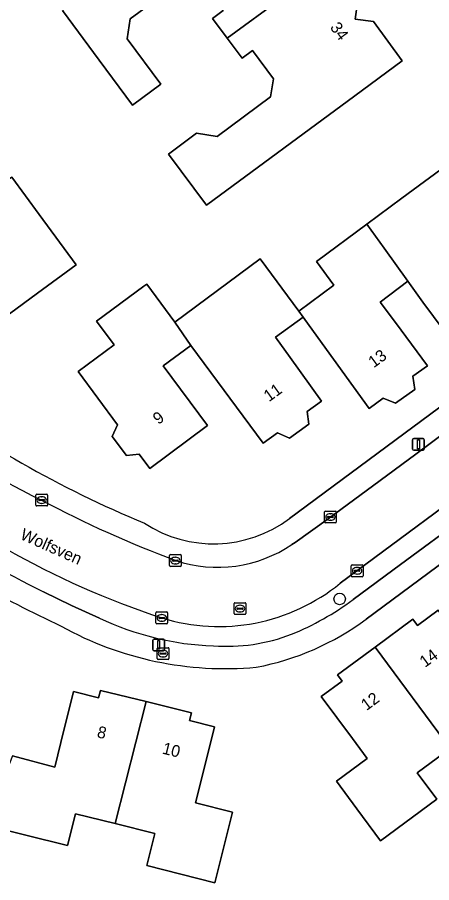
# Model space of a CAD drawing. Extents: x 163426 to 164192, y 380329 to 381641.
# Drawn here: x 163794 to 163829.1, y 381099.2 to 381172.6 of the extents above; entities that cross this region are included whole.
import ezdxf

# ---------------------------------------------------------------- set-up
doc = ezdxf.new("R2010")
doc.units = 0
for name, color, linetype in [('IMGEO_Boom', 7, 'Continuous'), ('IMGEO_Brandkraan', 7, 'Continuous'), ('IMGEO_Erf', 7, 'Continuous'), ('IMGEO_Kolk', 7, 'Continuous'), ('IMGEO_Lichtmast', 7, 'Continuous'), ('IMGEO_Openbare_ruimte_label', 7, 'Continuous'), ('IMGEO_Pand', 7, 'Continuous'), ('IMGEO_Pand_nummerreeks', 7, 'Continuous'), ('IMGEO_Parkeervlak_open', 7, 'Continuous'), ('IMGEO_Rijbaan_lokaal_open', 7, 'Continuous'), ('IMGEO_Rioolput', 7, 'Continuous'), ('IMGEO_Voetpad_open', 7, 'Continuous')]:
    doc.layers.add(name, color=color, linetype=linetype)

msp = doc.modelspace()

# ---------------------------------------------------------------- linework, layer by layer
at = {"layer": 'IMGEO_Boom'}
msp.add_circle((163821.325, 381123.271), 0.489, dxfattribs=at)
at = {"layer": 'IMGEO_Brandkraan'}
for p, q in [((163805.85, 381118.213), (163805.85, 381119.065)), ((163805.925, 381119.139), (163806.777, 381119.139)), ((163806.109, 381118.633), (163806.109, 381118.645)), ((163806.547, 381118.596), (163806.149, 381118.596)), ((163806.152, 381118.682), (163806.55, 381118.682)), ((163806.338, 381118.919), (163806.363, 381118.919)), ((163806.593, 381118.645), (163806.593, 381118.633)), ((163806.851, 381119.065), (163806.851, 381118.213)), ((163806.777, 381118.139), (163805.925, 381118.139)), ((163806.361, 381118.359), (163806.336, 381118.359))]:
    msp.add_line(p, q, dxfattribs=at)
for points in [[(163805.85, 381118.213), (163805.85, 381119.065)], [(163805.925, 381119.139), (163806.777, 381119.139)], [(163806.851, 381119.065), (163806.851, 381118.213)], [(163806.777, 381118.139), (163805.925, 381118.139)]]:
    msp.add_lwpolyline(points, dxfattribs=at)
for centre, radius, start, end in [((163805.927, 381119.063), 0.0765, 91.55205, 178.44795), ((163805.927, 381119.063), 0.0765, 91.55205, 178.44795), ((163806.149, 381118.642), 0.0403, 85.87752, 175.75265), ((163806.146, 381118.632), 0.0366, 178.93798, 274.71019), ((163806.55, 381118.639), 0.043, 264.86636, 352.45326), ((163806.554, 381118.644), 0.0386, 1.73085, 96.63898), ((163806.775, 381119.063), 0.0765, 1.55205, 88.44795), ((163806.775, 381119.063), 0.0765, 1.55205, 88.44795), ((163805.927, 381118.215), 0.0765, 181.55205, 268.44795), ((163805.927, 381118.215), 0.0765, 181.55205, 268.44795), ((163806.775, 381118.215), 0.0765, 271.55205, 358.44795), ((163806.775, 381118.215), 0.0765, 271.55205, 358.44795)]:
    msp.add_arc(centre, radius, start, end, dxfattribs=at)
for centre, major_axis, ratio, start_param, end_param in [((163806.337, 381118.639), (-0.387, 0.002), 0.722429, 4.712389, 7.853982), ((163806.362, 381118.639), (-0.39, 0.002), 0.717154, 1.570796, 4.712389)]:
    msp.add_ellipse(centre, major_axis=major_axis, ratio=ratio, start_param=start_param, end_param=end_param, dxfattribs=at)
at = {"layer": 'IMGEO_Erf'}
for points in [[(163808.098, 381175.797), (163803.557, 381172.436), (163803.32, 381170.757), (163806.172, 381166.906), (163803.761, 381165.12), (163800.933, 381168.938), (163797.815, 381173.15)], [(163823.048, 381175.267), (163822.643, 381172.432), (163824.185, 381172.212), (163826.637, 381168.889), (163822.614, 381165.921), (163810.036, 381156.641), (163806.817, 381160.989), (163809.196, 381162.75), (163810.928, 381162.477), (163815.469, 381165.839), (163815.714, 381167.372), (163813.94, 381169.768), (163813.047, 381169.11), (163811.798, 381170.798), (163810.549, 381172.486), (163811.441, 381173.144)], [(163831.091, 381144.772), (163828.366, 381148.43), (163827.112, 381150.199), (163824.75, 381148.44), (163826.045, 381146.701), (163828.772, 381143.04), (163827.539, 381142.153), (163827.706, 381141.032), (163826.045, 381139.855), (163825.025, 381140.29), (163823.826, 381139.407), (163819.474, 381145.443), (163818.239, 381147.156), (163815.888, 381145.462), (163817.123, 381143.748), (163819.788, 381140.05), (163818.564, 381139.167), (163818.724, 381138.092), (163817.063, 381136.915), (163816.044, 381137.35), (163814.834, 381136.478), (163808.708, 381144.764), (163806.375, 381143.039), (163810.128, 381137.963), (163805.221, 381134.335), (163804.334, 381135.534), (163803.239, 381135.422), (163802.051, 381137.037), (163802.48, 381138.042), (163799.148, 381142.548), (163802.197, 381144.803), (163800.71, 381146.814), (163804.731, 381149.787), (163804.974, 381149.966), (163807.353, 381146.748), (163814.593, 381152.101), (163817.864, 381147.677), (163820.841, 381149.877), (163819.354, 381151.889), (163823.618, 381155.041), (163826.6, 381157.234), (163830.864, 381160.386)], [(163793.533, 381159.015), (163795.851, 381155.871), (163798.995, 381151.607), (163795.715, 381149.189), (163793.332, 381147.432)], [(163817.071, 381130.093), (163847.678, 381152.747)], [(163851.582, 381142.287), (163823.576, 381121.569)], [(163793.575, 381109.96), (163797.188, 381109.011), (163797.698, 381111.091), (163798.761, 381115.426), (163800.89, 381114.881), (163801.053, 381115.52), (163804.907, 381114.568), (163808.761, 381113.616), (163808.597, 381112.979), (163810.719, 381112.431), (163809.643, 381108.113), (163809.113, 381105.987), (163812.245, 381105.207), (163811.562, 381102.482), (163810.744, 381099.218), (163804.976, 381100.669), (163805.657, 381103.379), (163802.299, 381104.224), (163798.941, 381105.068), (163798.26, 381102.358), (163791.258, 381104.106)]]:
    msp.add_lwpolyline(points, dxfattribs=at)
msp.add_lwpolyline([(163832.339, 381118.744), (163833.595, 381117.047), (163838.652, 381120.79), (163840.369, 381118.468), (163842.369, 381115.763), (163835.137, 381110.417), (163833.474, 381112.667), (163830.686, 381110.606), (163827.897, 381108.544), (163829.56, 381106.294), (163824.787, 381102.765), (163822.772, 381105.488), (163821.044, 381107.824), (163823.646, 381109.743), (163822.404, 381111.428), (163819.765, 381115.007), (163821.537, 381116.304), (163821.148, 381116.836), (163824.334, 381119.194), (163827.519, 381121.551), (163827.911, 381121.018), (163829.688, 381122.325)], close=True, dxfattribs=at)
for centre, radius, start, end in [((163840.706, 381216.197), 93.669, 233.26319, 247.44192), ((163810.638, 381138.638), 10.696, 236.74433, 306.97221), ((163850.773, 381233.409), 124.335, 237.116, 244.73978), ((163810.061, 381139.733), 22.64, 280.68675, 306.65263), ((163811.628, 381146.059), 28.695, 240.99562, 275.25988)]:
    msp.add_arc(centre, radius, start, end, dxfattribs=at)
at = {"layer": 'IMGEO_Kolk'}
for p, q in [((163795.563, 381131.229), (163795.563, 381132.081)), ((163795.638, 381132.155), (163796.49, 381132.155)), ((163795.865, 381131.698), (163796.263, 381131.698)), ((163796.051, 381131.935), (163796.076, 381131.935)), ((163796.564, 381132.081), (163796.564, 381131.229)), ((163796.49, 381131.155), (163795.638, 381131.155)), ((163795.822, 381131.649), (163795.822, 381131.661)), ((163796.26, 381131.612), (163795.862, 381131.612)), ((163796.074, 381131.375), (163796.049, 381131.375)), ((163796.306, 381131.661), (163796.306, 381131.649)), ((163820.041, 381129.792), (163820.041, 381130.644)), ((163820.116, 381130.718), (163820.968, 381130.718)), ((163820.3, 381130.212), (163820.3, 381130.224)), ((163820.343, 381130.261), (163820.741, 381130.261)), ((163820.529, 381130.498), (163820.554, 381130.498)), ((163820.784, 381130.224), (163820.784, 381130.212)), ((163821.042, 381130.644), (163821.042, 381129.792)), ((163820.968, 381129.718), (163820.116, 381129.718)), ((163820.738, 381130.175), (163820.34, 381130.175)), ((163820.552, 381129.938), (163820.527, 381129.938)), ((163806.897, 381126.103), (163806.897, 381126.955)), ((163806.972, 381127.029), (163807.824, 381127.029)), ((163807.156, 381126.523), (163807.156, 381126.535)), ((163807.199, 381126.572), (163807.597, 381126.572)), ((163807.385, 381126.809), (163807.41, 381126.809)), ((163807.64, 381126.535), (163807.64, 381126.523)), ((163807.898, 381126.955), (163807.898, 381126.103)), ((163807.824, 381126.029), (163806.972, 381126.029)), ((163807.594, 381126.486), (163807.196, 381126.486)), ((163807.408, 381126.249), (163807.383, 381126.249)), ((163822.303, 381125.232), (163822.303, 381126.084)), ((163822.378, 381126.158), (163823.23, 381126.158)), ((163822.791, 381125.938), (163822.816, 381125.938)), ((163823.304, 381126.084), (163823.304, 381125.232)), ((163823.23, 381125.158), (163822.378, 381125.158)), ((163822.562, 381125.652), (163822.562, 381125.664)), ((163823, 381125.615), (163822.602, 381125.615)), ((163822.605, 381125.701), (163823.003, 381125.701)), ((163822.814, 381125.378), (163822.789, 381125.378)), ((163823.046, 381125.664), (163823.046, 381125.652)), ((163805.816, 381122.167), (163806.668, 381122.167)), ((163805.741, 381121.241), (163805.741, 381122.093)), ((163806, 381121.661), (163806, 381121.673)), ((163806.438, 381121.624), (163806.04, 381121.624)), ((163806.043, 381121.71), (163806.441, 381121.71)), ((163806.229, 381121.947), (163806.254, 381121.947)), ((163806.484, 381121.673), (163806.484, 381121.661)), ((163806.742, 381122.093), (163806.742, 381121.241)), ((163806.668, 381121.167), (163805.816, 381121.167)), ((163806.252, 381121.387), (163806.227, 381121.387))]:
    msp.add_line(p, q, dxfattribs=at)
for points in [[(163795.563, 381131.229), (163795.563, 381132.081)], [(163795.638, 381132.155), (163796.49, 381132.155)], [(163796.564, 381132.081), (163796.564, 381131.229)], [(163796.49, 381131.155), (163795.638, 381131.155)], [(163820.041, 381129.792), (163820.041, 381130.644)], [(163820.116, 381130.718), (163820.968, 381130.718)], [(163821.042, 381130.644), (163821.042, 381129.792)], [(163820.968, 381129.718), (163820.116, 381129.718)], [(163806.897, 381126.103), (163806.897, 381126.955)], [(163806.972, 381127.029), (163807.824, 381127.029)], [(163807.898, 381126.955), (163807.898, 381126.103)], [(163807.824, 381126.029), (163806.972, 381126.029)], [(163822.303, 381125.232), (163822.303, 381126.084)], [(163822.378, 381126.158), (163823.23, 381126.158)], [(163823.304, 381126.084), (163823.304, 381125.232)], [(163823.23, 381125.158), (163822.378, 381125.158)], [(163805.816, 381122.167), (163806.668, 381122.167)], [(163805.741, 381121.241), (163805.741, 381122.093)], [(163806.742, 381122.093), (163806.742, 381121.241)], [(163806.668, 381121.167), (163805.816, 381121.167)]]:
    msp.add_lwpolyline(points, dxfattribs=at)
for centre, radius, start, end in [((163795.64, 381132.079), 0.0765, 91.55205, 178.44795), ((163795.64, 381132.079), 0.0765, 91.55205, 178.44795), ((163795.862, 381131.658), 0.0403, 85.87752, 175.75265), ((163796.267, 381131.66), 0.0386, 1.73085, 96.63898), ((163796.488, 381132.079), 0.0765, 1.55205, 88.44795), ((163796.488, 381132.079), 0.0765, 1.55205, 88.44795), ((163795.64, 381131.231), 0.0765, 181.55205, 268.44795), ((163795.64, 381131.231), 0.0765, 181.55205, 268.44795), ((163795.859, 381131.648), 0.0366, 178.93798, 274.71019), ((163796.263, 381131.655), 0.043, 264.86636, 352.45326), ((163796.488, 381131.231), 0.0765, 271.55205, 358.44795), ((163796.488, 381131.231), 0.0765, 271.55205, 358.44795), ((163820.118, 381130.642), 0.0765, 91.55205, 178.44795), ((163820.118, 381130.642), 0.0765, 91.55205, 178.44795), ((163820.34, 381130.221), 0.0403, 85.87752, 175.75265), ((163820.337, 381130.211), 0.0366, 178.93798, 274.71019), ((163820.741, 381130.218), 0.043, 264.86636, 352.45326), ((163820.745, 381130.223), 0.0386, 1.73085, 96.63898), ((163820.966, 381130.642), 0.0765, 1.55205, 88.44795), ((163820.966, 381130.642), 0.0765, 1.55205, 88.44795), ((163820.118, 381129.794), 0.0765, 181.55205, 268.44795), ((163820.118, 381129.794), 0.0765, 181.55205, 268.44795), ((163820.966, 381129.794), 0.0765, 271.55205, 358.44795), ((163820.966, 381129.794), 0.0765, 271.55205, 358.44795), ((163806.974, 381126.953), 0.0765, 91.55205, 178.44795), ((163806.974, 381126.953), 0.0765, 91.55205, 178.44795), ((163807.196, 381126.532), 0.0403, 85.87752, 175.75265), ((163807.601, 381126.534), 0.0386, 1.73085, 96.63898), ((163807.822, 381126.953), 0.0765, 1.55205, 88.44795), ((163807.822, 381126.953), 0.0765, 1.55205, 88.44795), ((163806.974, 381126.105), 0.0765, 181.55205, 268.44795), ((163806.974, 381126.105), 0.0765, 181.55205, 268.44795), ((163807.193, 381126.522), 0.0366, 178.93798, 274.71019), ((163807.597, 381126.529), 0.043, 264.86636, 352.45326), ((163807.822, 381126.105), 0.0765, 271.55205, 358.44795), ((163807.822, 381126.105), 0.0765, 271.55205, 358.44795), ((163822.38, 381126.082), 0.0765, 91.55205, 178.44795), ((163822.38, 381126.082), 0.0765, 91.55205, 178.44795), ((163823.228, 381126.082), 0.0765, 1.55205, 88.44795), ((163823.228, 381126.082), 0.0765, 1.55205, 88.44795), ((163822.38, 381125.234), 0.0765, 181.55205, 268.44795), ((163822.38, 381125.234), 0.0765, 181.55205, 268.44795), ((163822.602, 381125.661), 0.0403, 85.87752, 175.75265), ((163822.599, 381125.651), 0.0366, 178.93798, 274.71019), ((163823.003, 381125.658), 0.043, 264.86636, 352.45326), ((163823.007, 381125.663), 0.0386, 1.73085, 96.63898), ((163823.228, 381125.234), 0.0765, 271.55205, 358.44795), ((163823.228, 381125.234), 0.0765, 271.55205, 358.44795), ((163805.818, 381122.091), 0.0765, 91.55205, 178.44795), ((163805.818, 381122.091), 0.0765, 91.55205, 178.44795), ((163806.666, 381122.091), 0.0765, 1.55205, 88.44795), ((163806.666, 381122.091), 0.0765, 1.55205, 88.44795), ((163806.04, 381121.67), 0.0403, 85.87752, 175.75265), ((163806.037, 381121.66), 0.0366, 178.93798, 274.71019), ((163806.441, 381121.667), 0.043, 264.86636, 352.45326), ((163806.445, 381121.672), 0.0386, 1.73085, 96.63898), ((163805.818, 381121.243), 0.0765, 181.55205, 268.44795), ((163805.818, 381121.243), 0.0765, 181.55205, 268.44795), ((163806.666, 381121.243), 0.0765, 271.55205, 358.44795), ((163806.666, 381121.243), 0.0765, 271.55205, 358.44795)]:
    msp.add_arc(centre, radius, start, end, dxfattribs=at)
for centre, major_axis, ratio, start_param, end_param in [((163796.05, 381131.655), (-0.387, 0.002), 0.722429, 4.712389, 7.853982), ((163796.075, 381131.655), (-0.39, 0.002), 0.717154, 1.570796, 4.712389), ((163820.528, 381130.218), (-0.387, 0.002), 0.722429, 4.712389, 7.853982), ((163820.553, 381130.218), (-0.39, 0.002), 0.717154, 1.570796, 4.712389), ((163807.384, 381126.529), (-0.387, 0.002), 0.722429, 4.712389, 7.853982), ((163807.409, 381126.529), (-0.39, 0.002), 0.717154, 1.570796, 4.712389), ((163822.79, 381125.658), (-0.387, 0.002), 0.722429, 4.712389, 7.853982), ((163822.815, 381125.658), (-0.39, 0.002), 0.717154, 1.570796, 4.712389), ((163806.228, 381121.667), (-0.387, 0.002), 0.722429, 4.712389, 7.853982), ((163806.253, 381121.667), (-0.39, 0.002), 0.717154, 1.570796, 4.712389)]:
    msp.add_ellipse(centre, major_axis=major_axis, ratio=ratio, start_param=start_param, end_param=end_param, dxfattribs=at)
at = {"layer": 'IMGEO_Lichtmast'}
for p, q in [((163827.612, 381136.872), (163828.402, 381136.872)), ((163828.402, 381136.872), (163827.612, 381136.872)), ((163827.512, 381135.972), (163827.512, 381136.772)), ((163827.512, 381136.772), (163827.512, 381135.972)), ((163828.502, 381136.772), (163828.502, 381135.972)), ((163828.502, 381135.972), (163828.502, 381136.772)), ((163828.402, 381135.872), (163827.612, 381135.872)), ((163827.612, 381135.872), (163828.402, 381135.872)), ((163805.494, 381118.976), (163805.494, 381119.776)), ((163805.494, 381119.776), (163805.494, 381118.976)), ((163805.594, 381119.876), (163806.384, 381119.876)), ((163806.384, 381119.876), (163805.594, 381119.876)), ((163806.484, 381119.776), (163806.484, 381118.976)), ((163806.484, 381118.976), (163806.484, 381119.776)), ((163806.384, 381118.876), (163805.594, 381118.876)), ((163805.594, 381118.876), (163806.384, 381118.876))]:
    msp.add_line(p, q, dxfattribs=at)
for points in [[(163827.932, 381136.747), (163828.082, 381136.747), (163828.082, 381135.997), (163827.932, 381135.997), (163827.932, 381136.747)], [(163805.914, 381119.751), (163806.064, 381119.751), (163806.064, 381119.001), (163805.914, 381119.001), (163805.914, 381119.751)]]:
    msp.add_lwpolyline(points, dxfattribs=at)
for centre, start, end in [((163827.612, 381136.772), 90, 180), ((163827.612, 381136.772), 90, 180), ((163828.402, 381136.772), 0, 90), ((163828.402, 381136.772), 360, 90), ((163827.612, 381135.972), 180, 270), ((163827.612, 381135.972), 180, 270), ((163828.402, 381135.972), 270, 0), ((163828.402, 381135.972), 270, 0), ((163805.594, 381119.776), 90, 180), ((163805.594, 381119.776), 90, 180), ((163806.384, 381119.776), 0, 90), ((163806.384, 381119.776), 360, 90), ((163805.594, 381118.976), 180, 270), ((163805.594, 381118.976), 180, 270), ((163806.384, 381118.976), 270, 0), ((163806.384, 381118.976), 270, 0)]:
    msp.add_arc(centre, 0.1, start, end, dxfattribs=at)
at = {"layer": 'IMGEO_Pand'}
for points in [[(163821.215, 381177.742), (163819.368, 381180.236), (163816.558, 381180.651), (163816.783, 381182.179), (163814.382, 381185.389), (163797.815, 381173.15), (163800.933, 381168.938), (163803.761, 381165.12), (163806.172, 381166.906), (163803.32, 381170.757), (163803.557, 381172.436), (163808.098, 381175.797), (163809.64, 381175.577), (163811.441, 381173.144), (163810.549, 381172.486), (163811.798, 381170.798)], [(163826.637, 381168.889), (163824.185, 381172.212), (163822.643, 381172.432), (163823.048, 381175.267), (163821.215, 381177.742), (163811.798, 381170.798), (163813.047, 381169.11), (163813.94, 381169.768), (163815.714, 381167.372), (163815.469, 381165.839), (163810.928, 381162.477), (163809.196, 381162.75), (163806.817, 381160.989), (163810.036, 381156.641), (163822.614, 381165.921)], [(163834.32, 381155.544), (163830.864, 381160.386), (163826.6, 381157.234), (163823.618, 381155.041), (163825.11, 381153.022), (163827.112, 381150.199), (163828.366, 381148.43), (163831.091, 381144.772), (163832.291, 381145.658), (163833.31, 381145.223), (163834.971, 381146.4), (163834.805, 381147.516), (163835.998, 381148.397), (163833.267, 381152.044), (163831.966, 381153.781)], [(163798.995, 381151.607), (163795.851, 381155.871), (163793.533, 381159.015), (163792.727, 381158.423), (163792.851, 381158.255), (163790.84, 381156.772), (163786.196, 381153.423), (163784.666, 381152.32), (163782.575, 381150.799), (163783.458, 381149.599), (163783.026, 381148.586), (163784.214, 381146.971), (163785.311, 381147.083), (163786.194, 381145.883), (163789.916, 381148.627), (163791.559, 381149.838), (163793.332, 381147.432), (163795.715, 381149.189)], [(163827.112, 381150.199), (163825.11, 381153.022), (163823.618, 381155.041), (163819.354, 381151.889), (163820.841, 381149.877), (163817.864, 381147.677), (163818.239, 381147.156), (163819.474, 381145.443), (163823.826, 381139.407), (163825.025, 381140.29), (163826.045, 381139.855), (163827.706, 381141.032), (163827.539, 381142.153), (163828.772, 381143.04), (163826.045, 381146.701), (163824.75, 381148.44)], [(163818.239, 381147.156), (163817.864, 381147.677), (163814.593, 381152.101), (163807.353, 381146.748), (163808.708, 381144.764), (163814.834, 381136.478), (163816.044, 381137.35), (163817.063, 381136.915), (163818.724, 381138.092), (163818.564, 381139.167), (163819.788, 381140.05), (163817.123, 381143.748), (163815.888, 381145.462)], [(163808.708, 381144.764), (163807.353, 381146.748), (163804.974, 381149.966), (163804.731, 381149.787), (163800.71, 381146.814), (163802.197, 381144.803), (163799.148, 381142.548), (163802.48, 381138.042), (163802.051, 381137.037), (163803.239, 381135.422), (163804.334, 381135.534), (163805.221, 381134.335), (163810.128, 381137.963), (163806.375, 381143.039)], [(163832.339, 381118.744), (163829.688, 381122.325), (163827.911, 381121.018), (163827.519, 381121.551), (163824.334, 381119.194), (163830.686, 381110.606), (163833.474, 381112.667), (163835.137, 381110.417), (163842.369, 381115.763), (163840.369, 381118.468), (163838.652, 381120.79), (163833.595, 381117.047)], [(163824.334, 381119.194), (163821.148, 381116.836), (163821.537, 381116.304), (163819.765, 381115.007), (163822.404, 381111.428), (163823.646, 381109.743), (163821.044, 381107.824), (163822.772, 381105.488), (163824.787, 381102.765), (163829.56, 381106.294), (163827.897, 381108.544), (163830.686, 381110.606)], [(163804.907, 381114.568), (163801.053, 381115.52), (163800.89, 381114.881), (163798.761, 381115.426), (163797.698, 381111.091), (163797.188, 381109.011), (163793.575, 381109.96), (163791.258, 381104.106), (163798.26, 381102.358), (163798.941, 381105.068), (163802.299, 381104.224)], [(163809.643, 381108.113), (163810.719, 381112.431), (163808.597, 381112.979), (163808.761, 381113.616), (163804.907, 381114.568), (163802.299, 381104.224), (163805.657, 381103.379), (163804.976, 381100.669), (163810.744, 381099.218), (163811.562, 381102.482), (163812.245, 381105.207), (163809.113, 381105.987)]]:
    msp.add_lwpolyline(points, close=True, dxfattribs=at)
at = {"layer": 'IMGEO_Parkeervlak_open'}
for points in [[(163849.013, 381145.068), (163821.372, 381124.599)], [(163822.465, 381123.214), (163826.494, 381126.195), (163831.943, 381130.215), (163848.046, 381142.11)], [(163796.208, 381123.885), (163798.589, 381122.714), (163800.972, 381121.65)]]:
    msp.add_lwpolyline(points, dxfattribs=at)
for centre, radius, start, end in [((163850.759, 381233.827), 122.732, 238.47348, 243.61056), ((163828.367, 381189.232), 71.094, 240.17187, 251.86782), ((163811.076, 381137.232), 16.297, 252.74599, 309.18121), ((163808.131, 381142.583), 24.096, 292.2378, 306.50378), ((163811.481, 381143.742), 24.465, 244.55981, 267.97786), ((163811.715, 381134.709), 15.455, 265.92833, 290.98446)]:
    msp.add_arc(centre, radius, start, end, dxfattribs=at)
at = {"layer": 'IMGEO_Rijbaan_lokaal_open'}
for points in [[(163849.266, 381151.389), (163848.636, 381150.995), (163847.997, 381150.571), (163846.202, 381149.193), (163844.038, 381147.622), (163842.011, 381146.132), (163839.016, 381143.895), (163834.798, 381140.754), (163831.765, 381138.517), (163827.782, 381135.558), (163824.765, 381133.325), (163820.353, 381130.058), (163817.542, 381128.064), (163817.273, 381127.884)], [(163821.372, 381124.599), (163849.013, 381145.068)]]:
    msp.add_lwpolyline(points, dxfattribs=at)
for centre, radius, start, end in [((163825.779, 381192.582), 67.797, 231.71755, 243.9901), ((163841.803, 381217.978), 97.702, 242.07515, 249.40156), ((163828.367, 381189.232), 71.094, 240.17187, 251.86782), ((163810.959, 381137.266), 11.309, 251.81695, 303.93931), ((163811.076, 381137.232), 16.297, 252.74599, 309.18121)]:
    msp.add_arc(centre, radius, start, end, dxfattribs=at)
at = {"layer": 'IMGEO_Rioolput'}
for p, q in [((163812.374, 381122.026), (163812.374, 381122.878)), ((163812.449, 381122.952), (163813.301, 381122.952)), ((163813.375, 381122.878), (163813.375, 381122.026)), ((163812.633, 381122.446), (163812.633, 381122.458)), ((163813.071, 381122.409), (163812.673, 381122.409)), ((163812.676, 381122.495), (163813.074, 381122.495)), ((163812.885, 381122.172), (163812.86, 381122.172)), ((163812.862, 381122.732), (163812.887, 381122.732)), ((163813.117, 381122.458), (163813.117, 381122.446)), ((163813.301, 381121.952), (163812.449, 381121.952))]:
    msp.add_line(p, q, dxfattribs=at)
for points in [[(163812.374, 381122.026), (163812.374, 381122.878)], [(163812.449, 381122.952), (163813.301, 381122.952)], [(163813.375, 381122.878), (163813.375, 381122.026)], [(163813.301, 381121.952), (163812.449, 381121.952)]]:
    msp.add_lwpolyline(points, dxfattribs=at)
for centre, radius, start, end in [((163812.451, 381122.876), 0.0765, 91.55205, 178.44795), ((163812.451, 381122.876), 0.0765, 91.55205, 178.44795), ((163813.299, 381122.876), 0.0765, 1.55205, 88.44795), ((163813.299, 381122.876), 0.0765, 1.55205, 88.44795), ((163812.673, 381122.455), 0.0403, 85.87752, 175.75265), ((163812.67, 381122.445), 0.0366, 178.93798, 274.71019), ((163813.074, 381122.452), 0.043, 264.86636, 352.45326), ((163813.078, 381122.457), 0.0386, 1.73085, 96.63898), ((163812.451, 381122.028), 0.0765, 181.55205, 268.44795), ((163812.451, 381122.028), 0.0765, 181.55205, 268.44795), ((163813.299, 381122.028), 0.0765, 271.55205, 358.44795), ((163813.299, 381122.028), 0.0765, 271.55205, 358.44795)]:
    msp.add_arc(centre, radius, start, end, dxfattribs=at)
for centre, major_axis, ratio, start_param, end_param in [((163812.861, 381122.452), (-0.387, 0.002), 0.722429, 4.712389, 7.853982), ((163812.886, 381122.452), (-0.39, 0.002), 0.717154, 1.570796, 4.712389)]:
    msp.add_ellipse(centre, major_axis=major_axis, ratio=ratio, start_param=start_param, end_param=end_param, dxfattribs=at)
at = {"layer": 'IMGEO_Voetpad_open'}
for points in [[(163847.678, 381152.747), (163817.071, 381130.093)], [(163817.273, 381127.884), (163817.542, 381128.064), (163820.353, 381130.058), (163824.765, 381133.325), (163827.782, 381135.558), (163831.765, 381138.517), (163834.798, 381140.754), (163839.016, 381143.895), (163842.011, 381146.132), (163844.038, 381147.622), (163846.202, 381149.193), (163847.997, 381150.571), (163848.636, 381150.995), (163849.266, 381151.389), (163848.648, 381152.288)], [(163848.046, 381142.11), (163831.943, 381130.215), (163826.494, 381126.195), (163822.465, 381123.214)], [(163823.576, 381121.569), (163851.582, 381142.287)], [(163800.972, 381121.65), (163798.589, 381122.714), (163796.208, 381123.885)]]:
    msp.add_lwpolyline(points, dxfattribs=at)
for centre, radius, start, end in [((163840.706, 381216.197), 93.669, 233.26319, 247.44192), ((163825.779, 381192.582), 67.797, 231.71755, 243.9901), ((163841.803, 381217.978), 97.702, 242.07515, 249.40156), ((163810.638, 381138.638), 10.696, 236.74433, 306.97221), ((163850.773, 381233.409), 124.335, 237.116, 244.73978), ((163850.759, 381233.827), 122.732, 238.47348, 243.61056), ((163810.959, 381137.266), 11.309, 251.81695, 303.93931), ((163808.131, 381142.583), 24.096, 292.2378, 306.50378), ((163811.481, 381143.742), 24.465, 244.55981, 267.97786), ((163810.061, 381139.733), 22.64, 280.68675, 306.65263), ((163811.628, 381146.059), 28.695, 240.99562, 275.25988), ((163811.715, 381134.709), 15.455, 265.92833, 290.98446)]:
    msp.add_arc(centre, radius, start, end, dxfattribs=at)

# ---------------------------------------------------------------- texts
at = {"layer": 'IMGEO_Openbare_ruimte_label'}
msp.add_text('Wolfsven', height=1, rotation=336.10152, dxfattribs=at).set_placement((163794.163, 381128.376))
at = {"layer": 'IMGEO_Pand_nummerreeks'}
for s, rotation, p in [('34', 306.52585, (163820.462, 381171.715)), ('13', 36.29688, (163824.214, 381142.82)), ('11', 35.79267, (163815.333, 381139.944)), ('9', 36.47744, (163805.954, 381138.011)), ('14', 36.40574, (163828.562, 381117.42)), ('12', 36.40574, (163823.598, 381113.759)), ('8', 345.93962, (163800.691, 381111.561)), ('10', 345.93962, (163806.222, 381110.176))]:
    msp.add_text(s, height=1, rotation=rotation, dxfattribs=at).set_placement(p)

doc.saveas('drawing.dxf')
